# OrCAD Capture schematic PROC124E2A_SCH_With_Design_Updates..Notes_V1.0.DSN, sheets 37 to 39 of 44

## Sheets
37 36. OLDI DISPLAY INTERFACE: size C; title: OLDI DISPLAY INTERFACE
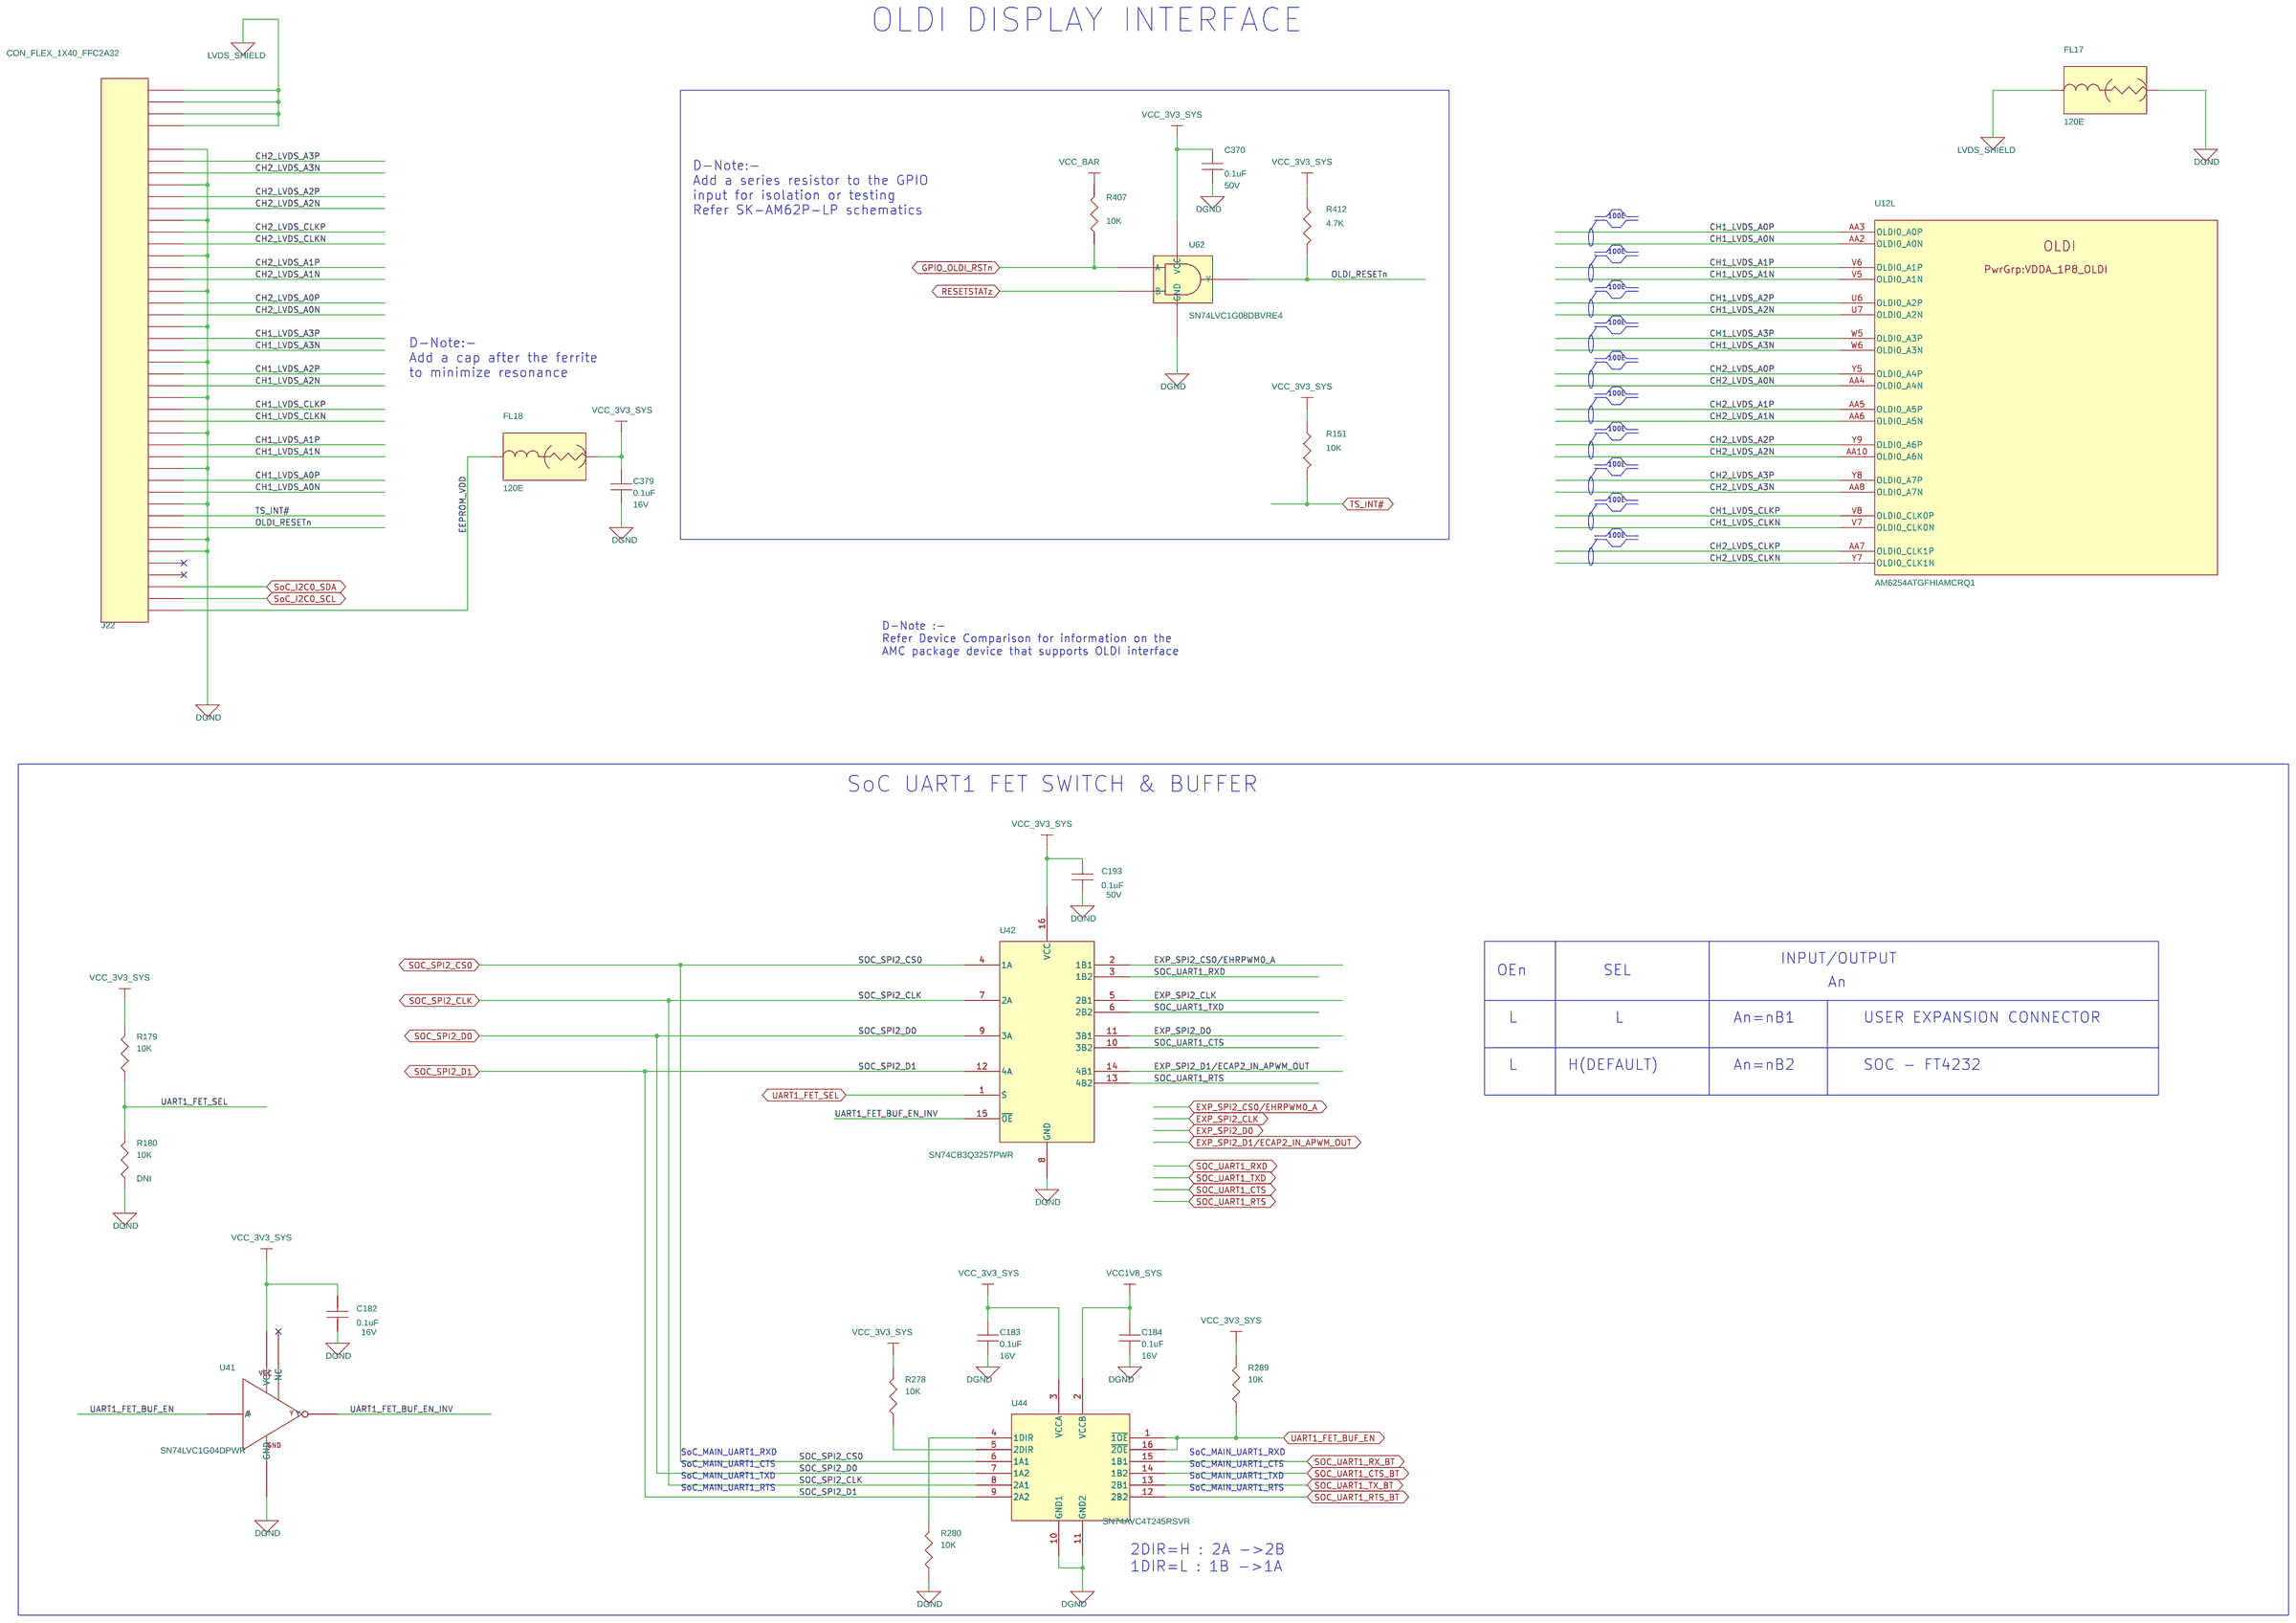
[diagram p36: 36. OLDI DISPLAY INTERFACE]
38 37. CSI INTERFACE & TEST LEDS: size C; title: CSI INTERFACE & USER TEST LEDS
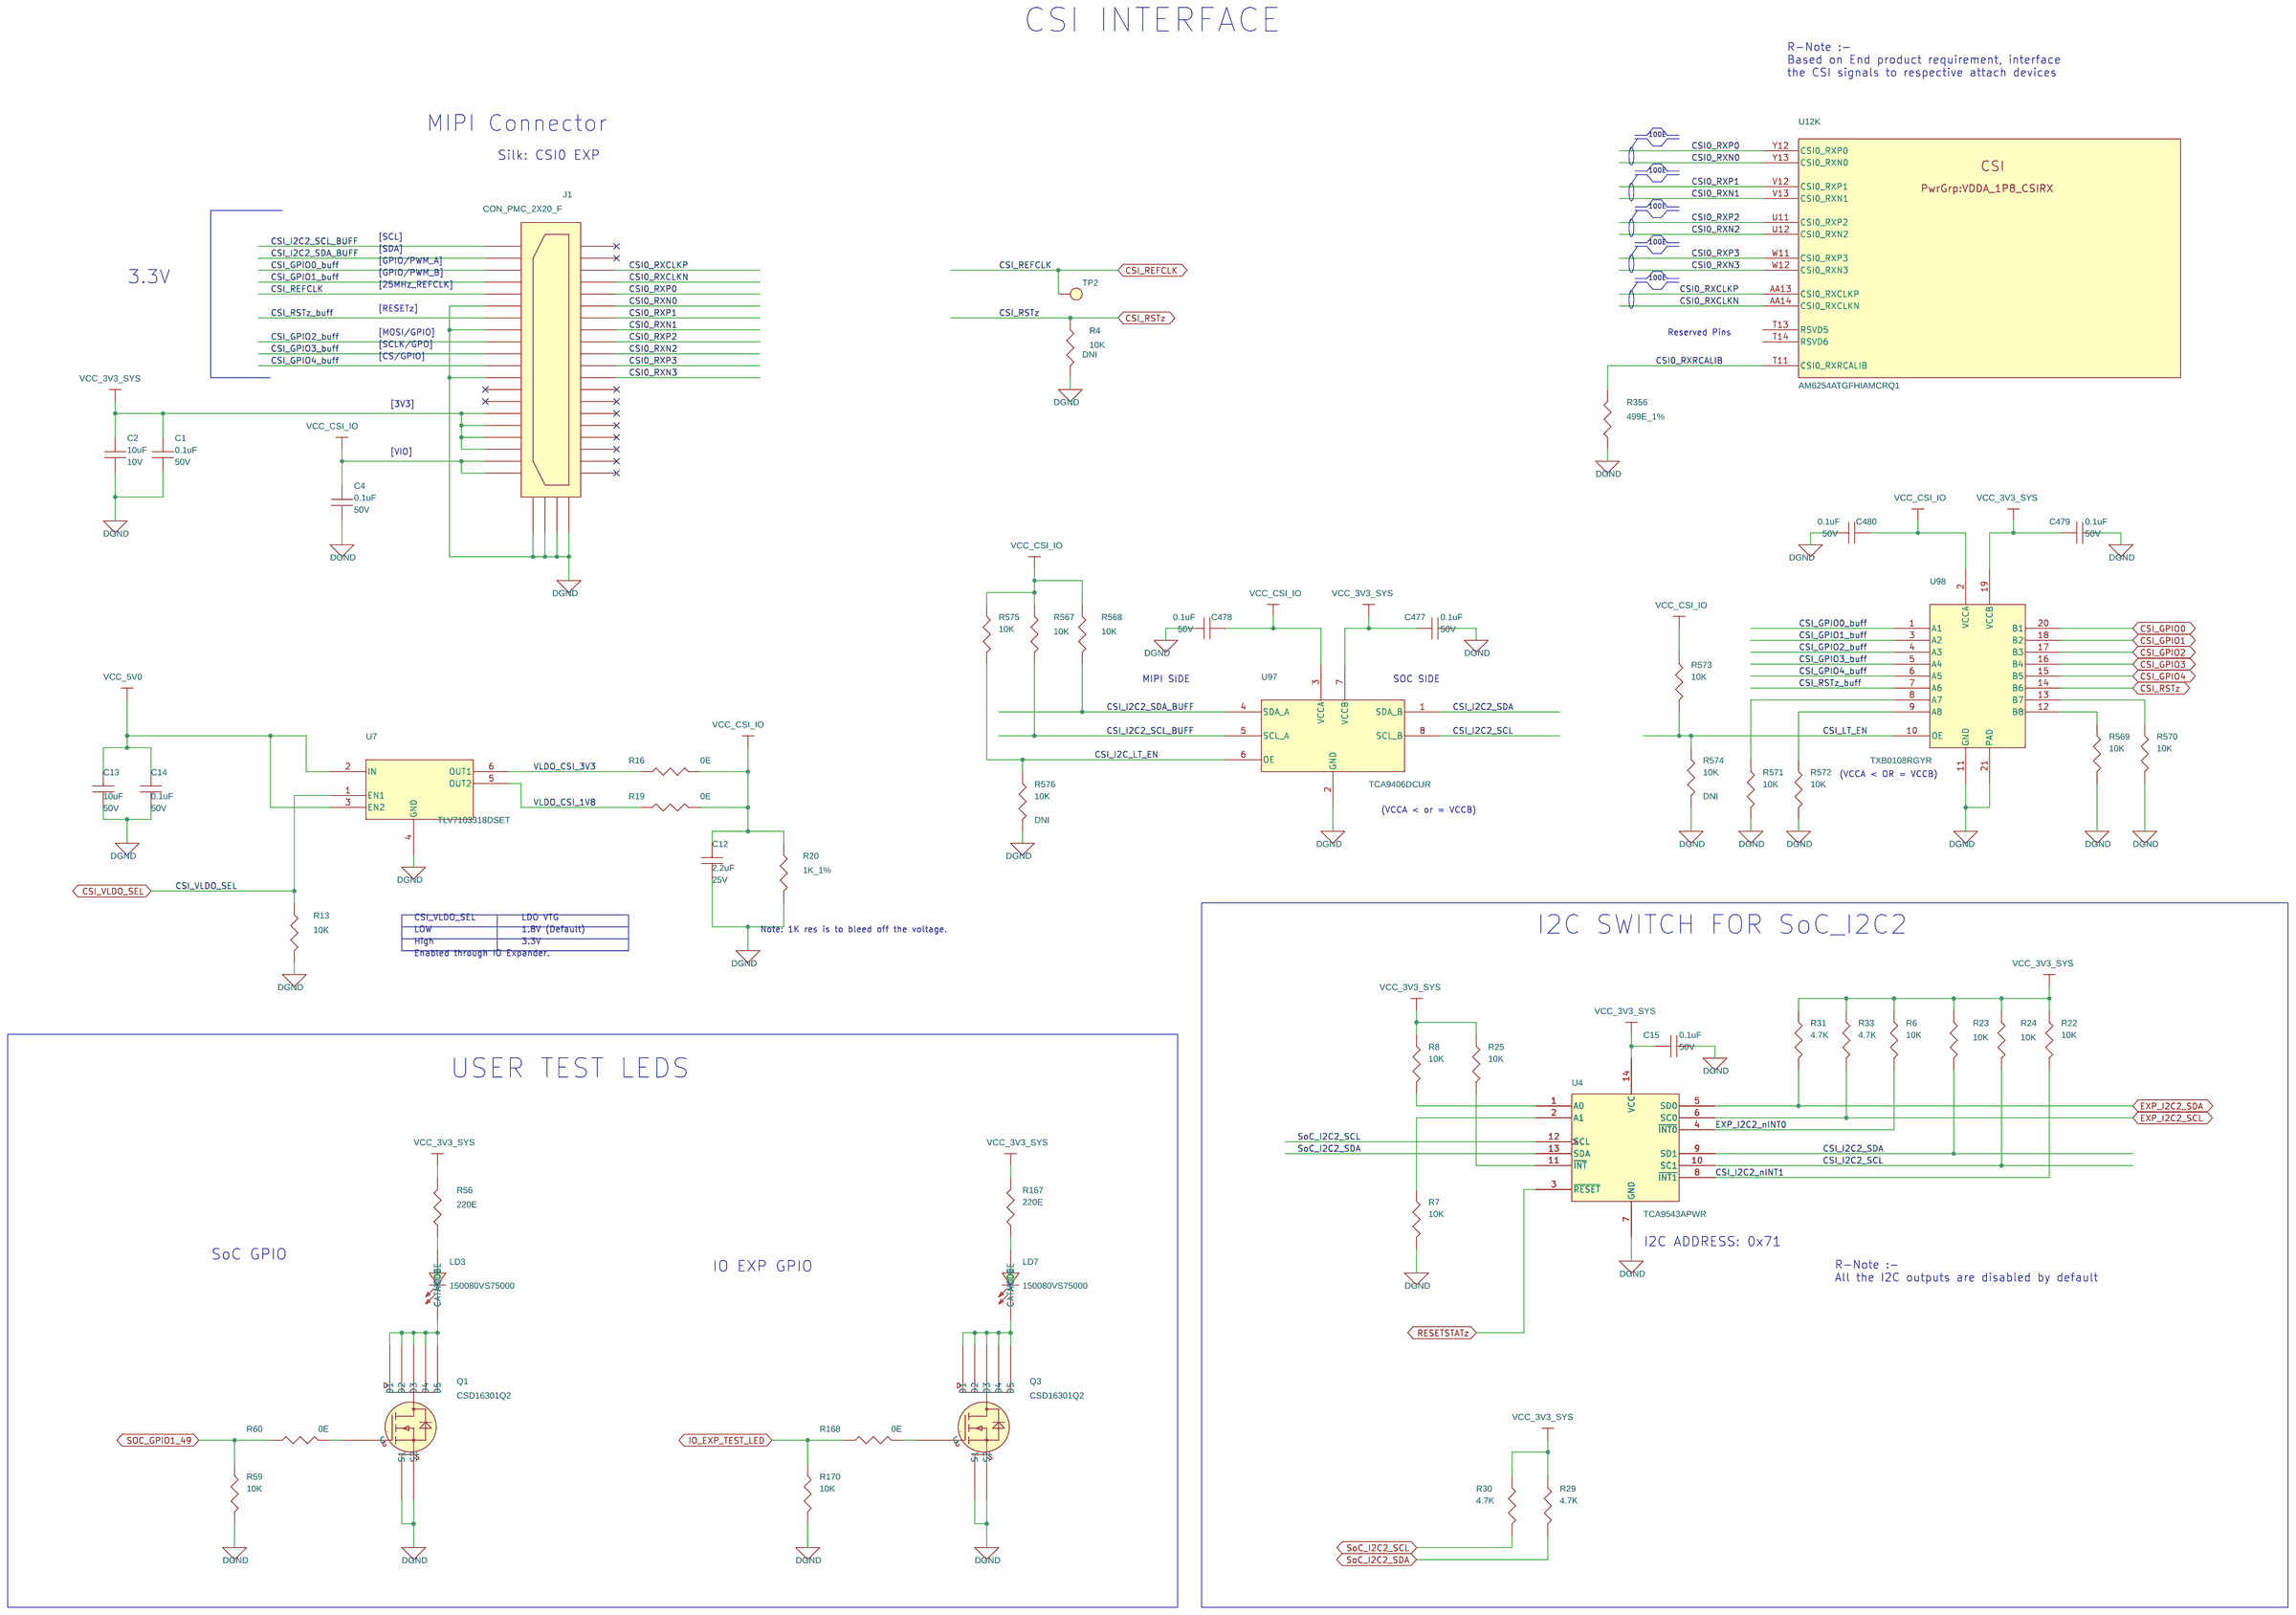
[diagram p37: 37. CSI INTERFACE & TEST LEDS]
39 39. IO EXPANDER: size C; title: IO EXPANDER
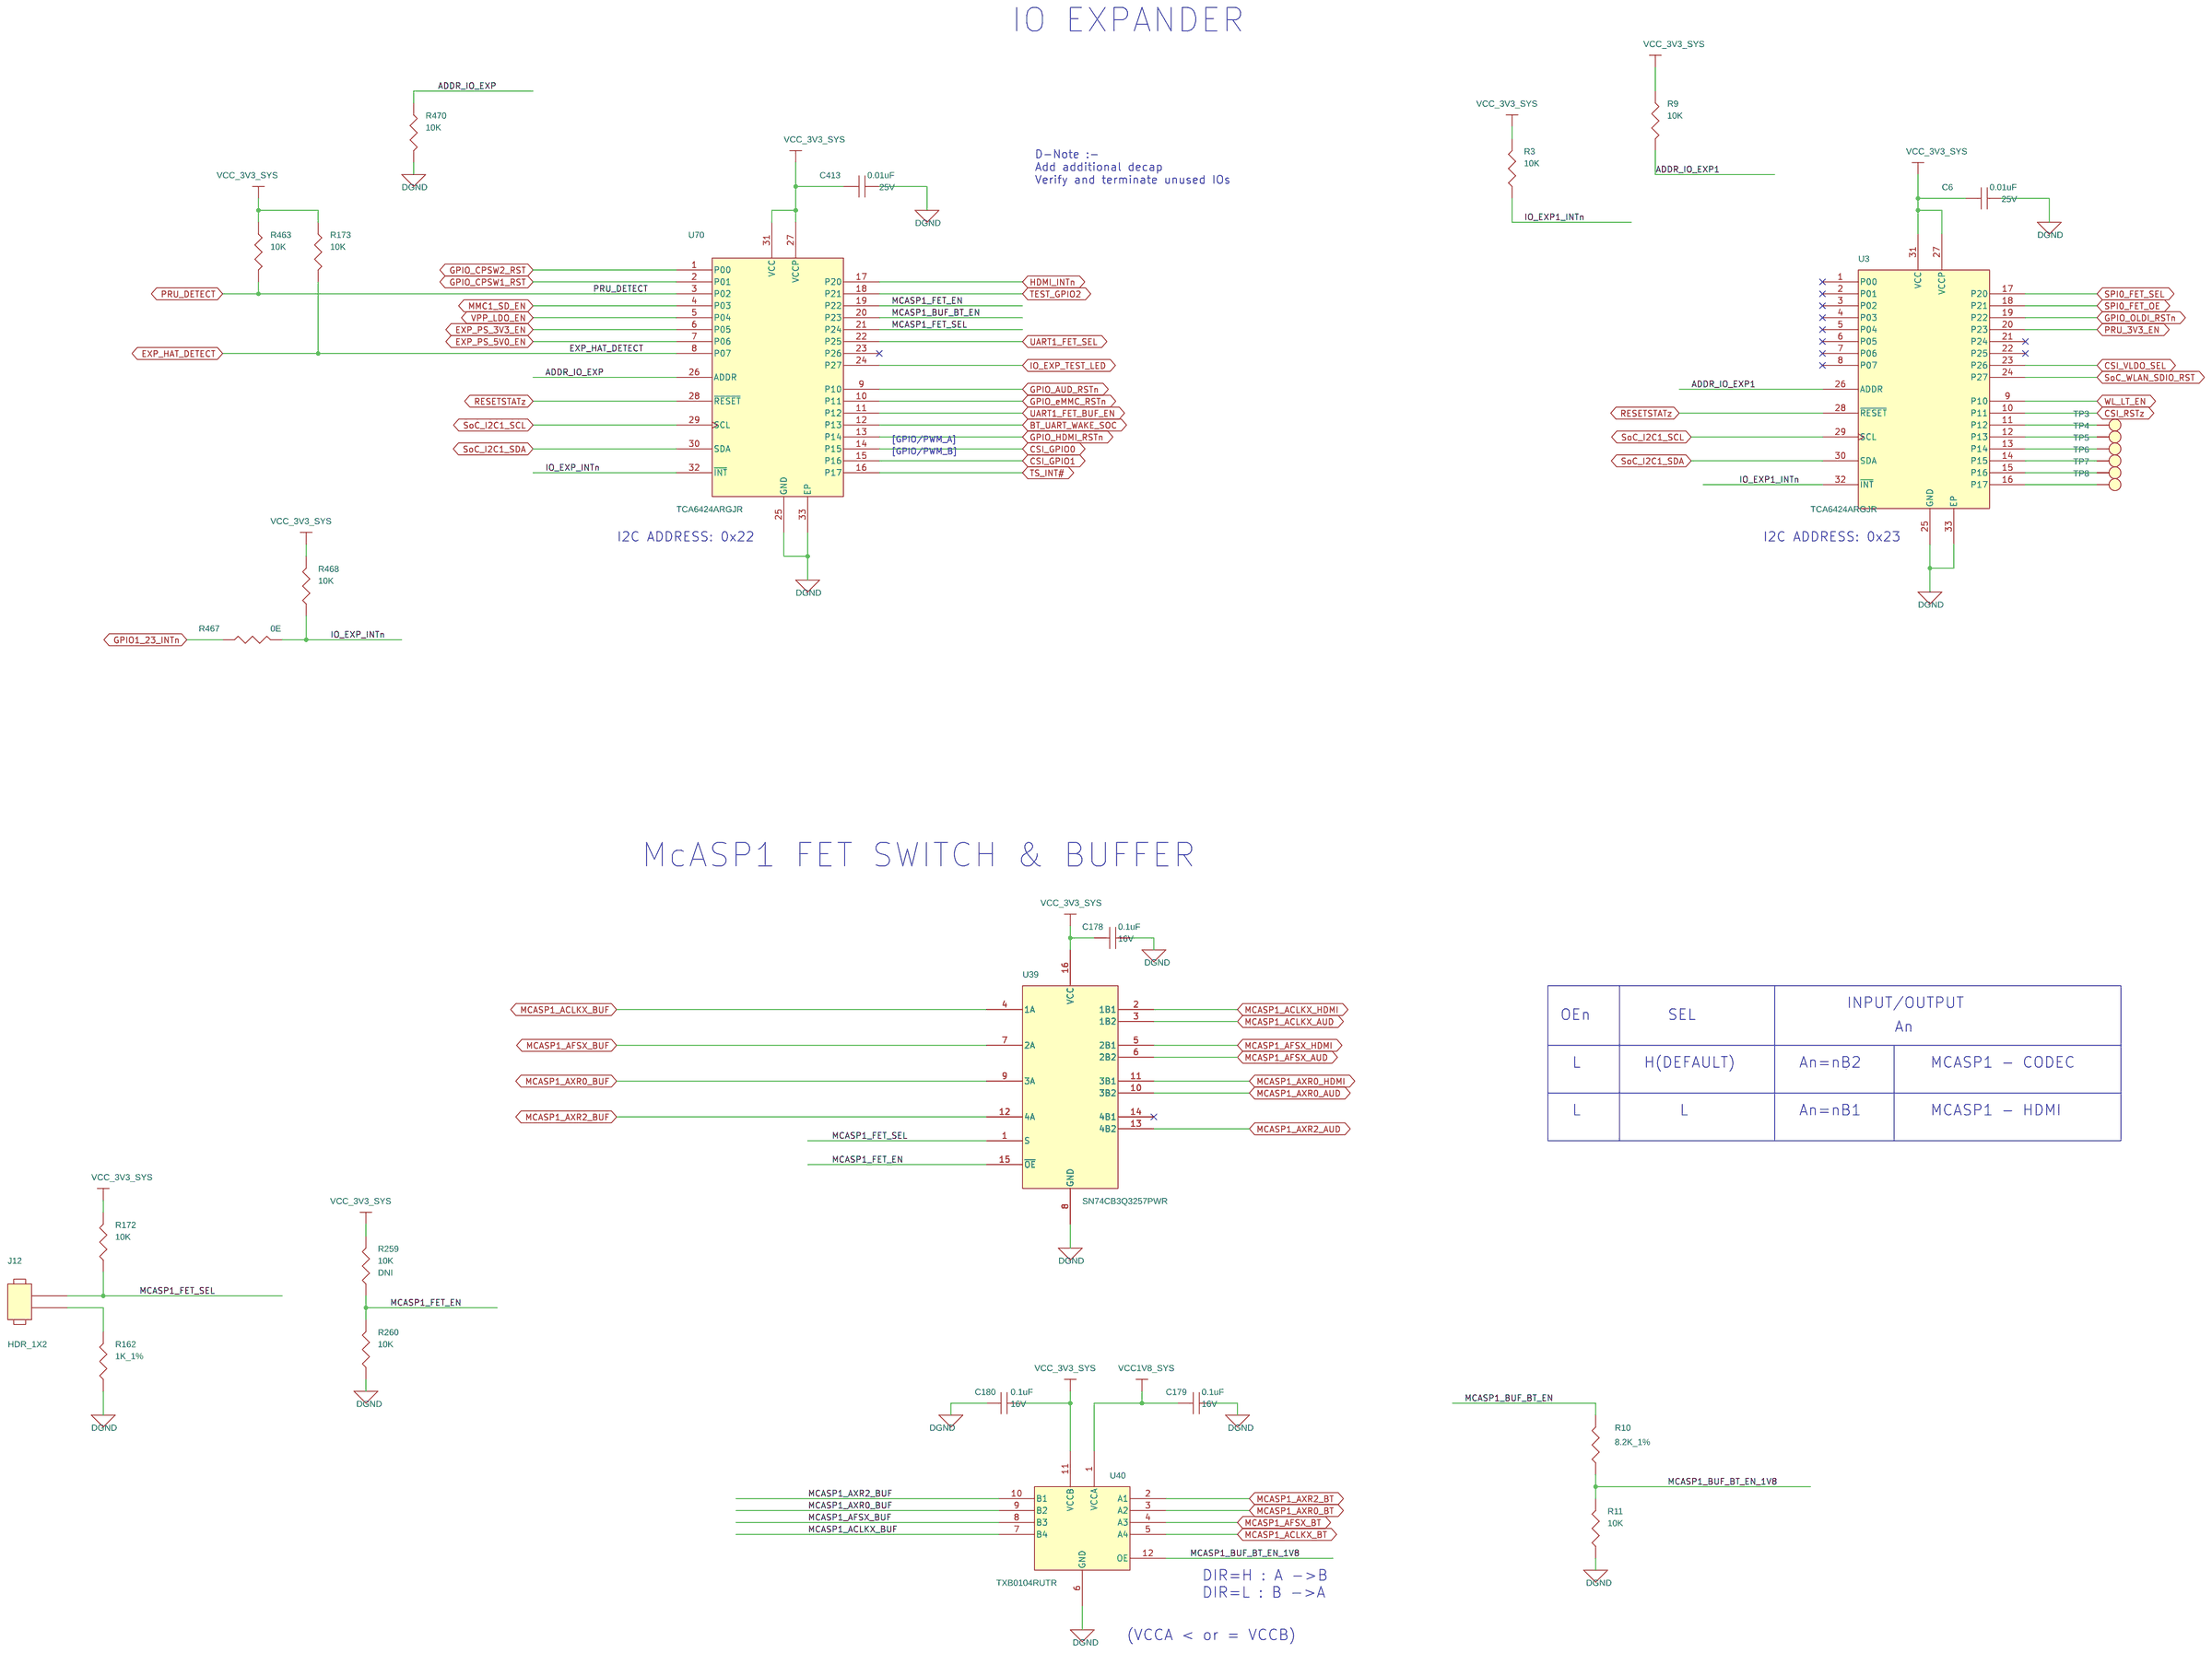
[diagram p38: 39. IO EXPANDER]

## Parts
sheet 15. SOC POWER CAPS
U12  AM6254ATGFHIAMCRQ1  [FCBGA441_31-49_680X680_2-6]  (sections A,B,C,D,E,F,G,H,I,J,K,L,M,N,O,P,Q,R)
sheet 36. OLDI DISPLAY INTERFACE
C182  0.1uF  [CAP0201_0-5]
C183  0.1uF  [CAP0201_0-5]
C184  0.1uF  [CAP0201_0-5]
C193  0.1uF  [CAP0402_0-75]
C370  0.1uF  [CAP0402_0-75]
C379  0.1uF  [CAP0201_0-5]
FL17  120E  [EMIFIL_BLM15A_0402_0-6]
FL18  120E  [EMIFIL_BLM15A_0402_0-6]
J22  CON_FLEX_1X40_FFC2A32  [CON_FLEX1X40_FFC2A32-40-T_S_S_S_4-3]
R151  10K  [RES0201_0-5]
R179  10K  [RES0201_0-5]
R180  10K  [RES0201_0-5]
R278  10K  [RES0201_0-5]
R280  10K  [RES0201_0-5]
R289  10K  [RES0201_0-5]
R407  10K  [RES0201_0-5]
R412  4.7K  [RES0201_0-5]
U41  SN74LVC1G04DPWR  [X2SON5_TLV7021_30X30_0-4]
U42  SN74CB3Q3257PWR  [TSSOP16_25-59_205X180]
U44  SN74AVC4T245RSVR  [UQFN16_TMUX1574_70X100_0-6]
U62  SN74LVC1G08DBVRE4  [SOT23-5]
sheet 37. CSI INTERFACE & TEST LEDS
C1  0.1uF  [CAP0402_0-75]
C2  10uF  [CAP0402_0-75]
C4  0.1uF  [CAP0402_0-75]
C12  2.2uF  [CAP0402_0-75]
C13  10uF  [CAP0805_1-5]
C14  0.1uF  [CAP0402_0-75]
C15  0.1uF  [CAP0402_0-75]
C477  0.1uF  [CAP0402_0-75]
C478  0.1uF  [CAP0402_0-75]
C479  0.1uF  [CAP0402_0-75]
C480  0.1uF  [CAP0402_0-75]
J1  CON_PMC_2X20_F  [CON_PMC2X20_QSH-020-01-D-DP-A_S_S_S_3-4]
LD3  150080VS75000  [LED_150080VS75000_80X50_SMD_0-8]
LD7  150080VS75000  [LED_150080VS75000_80X50_SMD_0-8]
Q1  CSD16301Q2  [WSON6_CSD13202Q2_80X80_0-8]
Q3  CSD16301Q2  [WSON6_CSD13202Q2_80X80_0-8]
R4  10K  [RES0201_0-5]
R6  10K  [RES0201_0-5]
R7  10K  [RES0201_0-5]
R8  10K  [RES0201_0-5]
R13  10K  [RES0201_0-5]
R16  0E  [RES0402_0-5]
R19  0E  [RES0402_0-5]
R20  1K_1%  [RES0402_0-5]
R22  10K  [RES0201_0-5]
R23  10K  [RES0201_0-5]
R24  10K  [RES0201_0-5]
R25  10K  [RES0201_0-5]
R29  4.7K  [RES0201_0-5]
R30  4.7K  [RES0201_0-5]
R31  4.7K  [RES0201_0-5]
R33  4.7K  [RES0201_0-5]
R56  220E  [RES0402_0-5]
R59  10K  [RES0201_0-5]
R60  0E  [RES0402_0-5]
R167  220E  [RES0402_0-5]
R168  0E  [RES0402_0-5]
R170  10K  [RES0201_0-5]
R356  499E_1%  [RES0402_0-5]
R567  10K  [RES0201_0-5]
R568  10K  [RES0201_0-5]
R569  10K  [RES0201_0-5]
R570  10K  [RES0201_0-5]
R571  10K  [RES0201_0-5]
R572  10K  [RES0201_0-5]
R573  10K  [RES0201_0-5]
R574  10K  [RES0201_0-5]
R575  10K  [RES0201_0-5]
R576  10K  [RES0201_0-5]
TP2  TP20_SMD  [TP20_SMD]
U4  TCA9543APWR  [TSSOP14_25-59_205X180_1-2]
U7  TLV7103318DSET  [WSON6_19-68_60X60]
U97  TCA9406DCUR  [VSSOP8_19-68_85X95]
U98  TXB0108RGYR  [QFN20_19-68_185X145_1]
sheet 39. IO EXPANDER
C6  0.01uF  [CAP0201_0-5]
C178  0.1uF  [CAP0201_0-5]
C179  0.1uF  [CAP0201_0-5]
C180  0.1uF  [CAP0201_0-5]
C413  0.01uF  [CAP0201_0-5]
J12  HDR_1X2  [HDR_1X2_90120-0122_S_T_5-6]
R3  10K  [RES0201_0-5]
R9  10K  [RES0201_0-5]
R10  8.2K_1%  [RES0201_0-5]
R11  10K  [RES0201_0-5]
R162  1K_1%  [RES0402_0-5]
R172  10K  [RES0201_0-5]
R173  10K  [RES0201_0-5]
R259  10K  [RES0201_0-5]
R260  10K  [RES0201_0-5]
R463  10K  [RES0201_0-5]
R467  0E  [RES0201_0-5]
R468  10K  [RES0201_0-5]
R470  10K  [RES0201_0-5]
TP3  TP20_SMD  [TP20_SMD]
TP4  TP20_SMD  [TP20_SMD]
TP5  TP20_SMD  [TP20_SMD]
TP6  TP20_SMD  [TP20_SMD]
TP7  TP20_SMD  [TP20_SMD]
TP8  TP20_SMD  [TP20_SMD]
U3  TCA6424ARGJR  [QFN32_19-68_200X200]
U39  SN74CB3Q3257PWR  [TSSOP16_25-59_205X180]
U40  TXB0104RUTR  [UQFN12_TXB0104RUT_70X80_0-6]
U70  TCA6424ARGJR  [QFN32_19-68_200X200]

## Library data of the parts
U12 = AM6254ATGFHIAMCRQ1_FCBGA441: IC AM62Q SoC MICROPROCESSOR FCBGA441; Chkd/date: PRADEEP/180324; Crtd /date: TAMILARASU/180324; Custom_Duty: 15%; Customs_HS_Code: 85423100; Distributor_name: NA; Distributor_part_number: NA; Footprint Path: Y:\MIS_DATABASE\Library\ALTIUM_TOOL\PCB_FOOTPRINTS\Altium_Footprint_Lib.PcbLib; Height: 2.57MM; Library Path: Y:\MIS_DATABASE\Library\ALTIUM_TOOL\SCHEMATICS_PARTS\MS_MICROPROCESSOR_Library.schlib; Mfr_name: TEXAS INSTRUMENTS; Mistral Part No: 141224030001-R; Package: FCBGA441; Part_type: ICS\DIGITAL\MICROPROCESSOR; Project: TI_AM62Q_BRD; RoHS: NA; Temperature: NA; Tolerance: NA; Voltage: NA; Wattage: NA; Weight: NA; Datasheet: Y:\MIS_DATABASE\DATASHEETS\ICS\DIGITAL\MICROCONTROLLER\AM62Q-SoC.PDF
C178-C180 C182-C184 C379 = CAP: CAP CERAMIC 0.1uF 16V 10% X5R 0201; Alt_Mfr_name: YAGEO AMERICA; Alt_Mfr_part_number: CC0402KRX5R8BB104; Chkd/date: MANIRAJA/230118; Crtd /date: MANIRAJA/230118; Custom_Duty: 15%; Customs_HS_Code: 85322990; Distributor_name: DIGIKEY; Distributor_part_number: 490-14305-1-ND; Footprint Path: Y:\MIS_DATABASE\Library\ALTIUM_TOOL\PCB_FOOTPRINTS\Altium_Footprint_Lib.PcbLib; Height: 0.33MM; Library Path: Y:\MIS_DATABASE\Library\ALTIUM_TOOL\SCHEMATICS_PARTS\MS_DISCRETE_Library.schlib; Mfr_name: MURATA; Mfr_part_number: GRM033R61C104KE14D; Mistral Part No: 120009030072-R; Package: 0201; Part_type: CAPACITORS\CERAMIC; Project: TI_MAXIE_CPB; RoHS: RoHS; Temperature: -55°C+85°C; Tolerance: 10%; Voltage: 16V; Wattage: NA; Weight: 0.33mg; Datasheet: Y:\MIS_DATABASE\DATASHEETS\CAPACITORS\GRM033R61C104KE14.PDF
C1 C4 C14 C15 C193 C370 C477-C480 = CAP: CAP CERAMIC 0.1uF 50V 10% X7R 0402; Alt_Mfr_name: YAGEO AMERICA; Alt_Mfr_part_number: CC0402KRX5R8BB104; Chkd/date: MANIRAJA/261020; Crtd /date: ALVY/211020; Custom_Duty: 15%; Customs_HS_Code: 85322990; Distributor_name: DIGIKEY; Distributor_part_number: 490-10700-1-ND; Footprint Path: Y:\MIS_DATABASE\Library\ALTIUM_TOOL\PCB_FOOTPRINTS\Altium_Footprint_Lib.PcbLib; Height: 0.55MM; Library Path: Y:\MIS_DATABASE\Library\ALTIUM_TOOL\SCHEMATICS_PARTS\MS_DISCRETE_Library.schlib; Mfr_name: MURATA; Mfr_part_number: GRM155R71H104KE14D; Mistral Part No: 120011100014-R; Package: 0402; Part_type: CAPACITORS\CERAMIC; Project: J7_CP; RoHS: RoHS; Temperature: -55°C+125°C; Tolerance: 10%; Voltage: 50V; Wattage: NA; Weight: 3.1mg; Datasheet: Y:\MIS_DATABASE\DATASHEETS\CAPACITORS\GRM155R71H104KE14.PDF
FL17 FL18 = EMIFILTER_IND: IND FERRITE BEAD CHIP 120E 2A 0402; Chkd/date: NAVEED/241114; Crtd /date: USMAN/170613; Custom_Duty: 24%; Customs_HS_Code: 85369090; Distributor_name: DIGIKEY; Distributor_part_number: 490-9656-1-ND; Footprint Path: Y:\MIS_DATABASE\Library\ALTIUM_TOOL\PCB_FOOTPRINTS\Altium_Footprint_Lib.PcbLib; Height: 0.55MM; Library Path: Y:\MIS_DATABASE\Library\ALTIUM_TOOL\SCHEMATICS_PARTS\MS_FILTER_Library.schlib; Mfr_name: MURATA; Mfr_part_number: BLM15PX121SN1D; Mistral Part No: 130013060022-R; Package: 0402; Part_type: INDUCTOR; Project: GEN_3-8; RoHS: RoHS; Temperature: -55°C+125°C; Tolerance: 25%; Voltage: NA; Wattage: NA; Weight: 1mg; Datasheet: Y:\MIS_DATABASE\DATASHEETS\DISCRETES\INDUCTORS\BLM15-SN1-SER.PDF
J22 = CON_FLEX_40X1_SH4: CON FPC 1X40 0.50MM PITCH FEMALE ST SMD; Chkd/date: MANIRAJA/061021; Crtd /date: ALVY/041021; Custom_Duty: 24%; Customs_HS_Code: 85369090; Distributor_name: DIGIKEY; Distributor_part_number: 2073-FFC2A32-40-TCT-ND; Footprint Path: Y:\MIS_DATABASE\Library\ALTIUM_TOOL\PCB_FOOTPRINTS\Altium_Footprint_Lib.PcbLib; Height: 4.25MM; Library Path: Y:\MIS_DATABASE\Library\ALTIUM_TOOL\SCHEMATICS_PARTS\MS_CONNECTOR_Library.schlib; Mfr_name: GCT; Mfr_part_number: FFC2A32-40-T; Mistral Part No: 150021100004-R; Package: SMD; Part_type: CONNECTOR\FPC; Project: TI_AM62x SKEVM_BRD; RoHS: RoHS; Temperature: -25°C+85°C; Tolerance: NA; Voltage: NA; Wattage: NA; Weight: 710mg; Datasheet: Y:\MIS_DATABASE\DATASHEETS\CONNECTORS\FFC2A32.PDF
R3 R6-R9 R11 R13 R22-R25 R59 R151 R170 R172 R173 R179 R260 R278 R280 R289 R407 R463 R468 R470 R567-R573 R575 = RESISTOR: RES 10K 1/20W 5% 0201; Chkd/date: MANIRAJA/050517; Crtd /date: MANIRAJA/050517; Custom_Duty: 15%; Customs_HS_Code: 85332119; Distributor_name: DIGIKEY; Distributor_part_number: 311-10KNCT-ND; Footprint Path: Y:\MIS_DATABASE\Library\ALTIUM_TOOL\PCB_FOOTPRINTS\Altium_Footprint_Lib.PcbLib; Height: 0.26MM; Library Path: Y:\MIS_DATABASE\Library\ALTIUM_TOOL\SCHEMATICS_PARTS\MS_DISCRETE_Library.schlib; Mfr_name: YAGEO AMERICA; Mfr_part_number: RC0201JR-0710KL; Mistral Part No: 110010070051-R; Package: 0201; Part_type: RESISTORS\FIXED; Project: GOLDEN-I LITE; RoHS: RoHS; Temperature: -55°C+125°C; Tolerance: 5%; Voltage: NA; Wattage: 1/20W; Weight: 0.17mg; Datasheet: Y:\MIS_DATABASE\DATASHEETS\RESISTORS\RCXXXXL-SER_MAR18.PDF
R4 R180 R259 R574 R576 = RESISTOR: RES 10K 1/20W 5% 0201; Assembly_Instruction: DNI; Chkd/date: MANIRAJA/050517; Crtd /date: MANIRAJA/050517; Custom_Duty: 15%; Customs_HS_Code: 85332119; Distributor_name: DIGIKEY; Distributor_part_number: 311-10KNCT-ND; Footprint Path: Y:\MIS_DATABASE\Library\ALTIUM_TOOL\PCB_FOOTPRINTS\Altium_Footprint_Lib.PcbLib; Height: 0.26MM; Library Path: Y:\MIS_DATABASE\Library\ALTIUM_TOOL\SCHEMATICS_PARTS\MS_DISCRETE_Library.schlib; Mfr_name: YAGEO AMERICA; Mfr_part_number: RC0201JR-0710KL; Mistral Part No: 110010070051-R; Package: 0201; Part_type: RESISTORS\FIXED; Project: GOLDEN-I LITE; RoHS: RoHS; Temperature: -55°C+125°C; Tolerance: 5%; Voltage: NA; Wattage: 1/20W; Weight: 0.17mg; Datasheet: Y:\MIS_DATABASE\DATASHEETS\RESISTORS\RCXXXXL-SER_MAR18.PDF
R29-R31 R33 R412 = RESISTOR: RES 4.7K 1/20W 5% 0201; Chkd/date: MANIRAJA/200921; Crtd /date: ALVY/200921; Custom_Duty: 15%; Customs_HS_Code: 85332119; Distributor_name: DIGIKEY; Distributor_part_number: 311-4.7KNCT-ND; Footprint Path: Y:\MIS_DATABASE\Library\ALTIUM_TOOL\PCB_FOOTPRINTS\Altium_Footprint_Lib.PcbLib; Height: 0.26MM; Library Path: Y:\MIS_DATABASE\Library\ALTIUM_TOOL\SCHEMATICS_PARTS\MS_DISCRETE_Library.schlib; Mfr_name: YAGEO AMERICA; Mfr_part_number: RC0201JR-074K7L; Mistral Part No: 110021090007-R; Package: 0201; Part_type: RESISTORS\FIXED; Project: TI_AM62x SKEVM_BRD; RoHS: RoHS; Temperature: -55°C+125°C; Tolerance: 5%; Voltage: NA; Wattage: 1/20W; Weight: 0.17mg; Datasheet: Y:\MIS_DATABASE\DATASHEETS\RESISTORS\RCXXXXL-SER_MAR18.PDF
U41 = SN74LVC1G04DCKR_SC70-5: IC SINGLE INVERTER GATE X2SON5; Chkd/date: MANIRAJA/141020; Crtd /date: ALVY/131020; Custom_Duty: 15%; Customs_HS_Code: 85423100; Distributor_name: DIGIKEY; Distributor_part_number: 296-37758-1-ND; Footprint Path: Y:\MIS_DATABASE\Library\ALTIUM_TOOL\PCB_FOOTPRINTS\Altium_Footprint_Lib.PcbLib; Height: 0.40MM; Library Path: Y:\MIS_DATABASE\Library\ALTIUM_TOOL\SCHEMATICS_PARTS\MS_GATE_Library.schlib; Mfr_name: TEXAS INSTRUMENTS; Mistral Part No: 141020100010-R; Package: X2SON5; Part_type: ICS\DIGITAL\GATES; Project: AM64X_SKEVM; RoHS: RoHS; Temperature: -40°C+125°C; Tolerance: NA; Voltage: NA; Wattage: NA; Weight: 0.6mg; Datasheet: Y:\MIS_DATABASE\DATASHEETS\ICS\DIGITAL\GATES\SN74LVC1G04XX.PDF
U42 = SN74CB3Q3257PWR_TSSOP16: IC 4BIT 1-OF-2 FET MULTIPLEXER/DEMULTIPLEXER TSSOP16; Chkd/date: SUHAS/251010; Crtd /date: USMAN/060109; Custom_Duty: 15%; Customs_HS_Code: 85423100; Distributor_name: DIGIKEY; Distributor_part_number: 296-19138-1-ND; Footprint Path: Y:\MIS_DATABASE\Library\ALTIUM_TOOL\PCB_FOOTPRINTS\Altium_Footprint_Lib.PcbLib; Footprint Ref: TSSOP16_25-59_205X180_1-2; Height: 1.20MM; Library Path: Y:\MIS_DATABASE\Library\ALTIUM_TOOL\SCHEMATICS_PARTS\MS_COMBINATIONAL_Library.schlib; MECHANICAL 3D STEP FILE: TSSOP16_25-59_205X180_1-2; Mfr_name: TEXAS INSTRUMENTS; Mistral Part No: 141009030117-R; Package: TSSOP16; Part_type: ICS\DIGITAL\COMBINATIONAL; Project: OMAP_EVM; RoHS: Sb/ Br FREE; Temperature: -40°C+85°C; Datasheet: Y:\MIS_DATABASE\DATASHEETS\ICS\DIGITAL\COMBINATIONAL\SN74CB3Q3257.PDF
U44 = SN74AVC4T245RSV_UQFN16: IC 2-BIT BUS TRANSCEIVER WITH CONFIGURABLE VOLTAGE TRANSLATION AND 3 STATE O/P UQFN16; Chkd/date: MANIRAJA/040520; Crtd /date: BAVISH/190411; Custom_Duty: 15%; Customs_HS_Code: 85423100; Distributor_name: DIGIKEY; Distributor_part_number: 296-24366-1-ND; Footprint Path: Y:\MIS_DATABASE\Library\ALTIUM_TOOL\PCB_FOOTPRINTS\Altium_Footprint_Lib.PcbLib; Height: 0.55MM; Library Path: Y:\MIS_DATABASE\Library\ALTIUM_TOOL\SCHEMATICS_PARTS\MS_BUSDRIVERTRANSCEIVER_Library.schlib; Mfr_name: TEXAS INSTRUMENTS; Mistral Part No: 141011040011-R; Package: UQFN16; Part_type: ICS\DIGITAL\BUSTRANSCEIVER; Project: HMC; RoHS: RoHS; Temperature: -40°C+85°C; Tolerance: NA; Voltage: NA; Wattage: NA; Weight: 41mg; Datasheet: Y:\MIS_DATABASE\DATASHEETS\ICS\DIGITAL\BUSTRANSCEIVER\SN74AVC4T245-SER.PDF
U62 = SN74LVC1G08DBVRE4_SOT23-5: IC SINGLE 2-INPUT POSITIVE AND GATE SOT23-5; Chkd/date: SUHAS/221010; Crtd /date: USMAN/151008; Custom_Duty: 15%; Customs_HS_Code: 85423100; Distributor_name: DIGIKEY; Distributor_part_number: SN74LVC1G08DBVRE4-ND; Height: 1.45MM; Mfr_name: TEXAS INSTRUMENTS; Mistral Part No: 141009060026-R; Part_type: ICS\DIGITAL\GATES; Project: KHAN_MAIN; RoHS: Sb/ Br FREE; Temperature: -40°C+85°C; Datasheet: Y:\MIS_DATABASE\DATASHEETS\ICS\DIGITAL\GATES\SN74LVC1G08.PDF
C2 = CAP: CAP CERAMIC 10uF 10V 20% X5R 0402; Chkd/date: MANIRAJA/300520; Crtd /date: ALVY/260520; Custom_Duty: 15%; Customs_HS_Code: 85322990; Distributor_name: DIGIKEY; Distributor_part_number: 490-GRM155R61A106ME11DTR-ND; Footprint Path: Y:\MIS_DATABASE\Library\ALTIUM_TOOL\PCB_FOOTPRINTS\Altium_Footprint_Lib.PcbLib; Height: 0.55MM; Library Path: Y:\MIS_DATABASE\Library\ALTIUM_TOOL\SCHEMATICS_PARTS\MS_DISCRETE_Library.schlib; Mfr_name: MURATA; Mfr_part_number: GRM155R61A106ME11D; Mistral Part No: 120013110019-R; Package: 0402; Part_type: CAPACITORS\CERAMIC; Project: QCS610_NANOSOM; RoHS: RoHS; Temperature: -55°C+85°C; Tolerance: 20%; Voltage: 10V; Wattage: NA; Weight: 3.1mg; Datasheet: Y:\MIS_DATABASE\DATASHEETS\CAPACITORS\MURATA-GXX-SER_NOV17.PDF
C12 = CAP: CAP CERAMIC 2.2uF 25V 10% X5R 0402; Chkd/date: ALVY/010721; Crtd /date: MANIRAJA/010721; Custom_Duty: 15%; Customs_HS_Code: 85322990; Distributor_name: DIGIKEY; Distributor_part_number: 490-12703-1-ND; Footprint Path: Y:\MIS_DATABASE\Library\ALTIUM_TOOL\PCB_FOOTPRINTS\Altium_Footprint_Lib.PcbLib; Height: 0.70MM; Library Path: Y:\MIS_DATABASE\Library\ALTIUM_TOOL\SCHEMATICS_PARTS\MS_DISCRETE_Library.schlib; Manufacturer: MURATA; Mfr_name: MURATA; Mfr_part_number: GRM155R61E225KE11D; Mistral Part No: 120015120001-R; Package: 0402; Part_type: CAPACITORS\CERAMIC; Project: TI_AM263X_CC; RoHS: RoHS; Temperature: -55°C+85°C; Tolerance: 10%; Voltage: 25V; Wattage: NA; Weight: 1.5mg; Datasheet: Y:\MIS_DATABASE\DATASHEETS\CAPACITORS\GRM155R61E225KE11.PDF
C13 = CAP: CAP CERAMIC 10uF 50V 10% X5R 0805; Chkd/date: MANIRAJA/010321; Crtd /date: ALVY/010321; Custom_Duty: 15%; Customs_HS_Code: 85322990; Distributor_name: DIGIKEY; Distributor_part_number: 490-18663-1-ND; Footprint Path: Y:\MIS_DATABASE\Library\ALTIUM_TOOL\PCB_FOOTPRINTS\Altium_Footprint_Lib.PcbLib; Height: 1.45MM; Library Path: Y:\MIS_DATABASE\Library\ALTIUM_TOOL\SCHEMATICS_PARTS\MS_DISCRETE_Library.schlib; Manufacturer: MURATA; Mfr_name: MURATA; Mfr_part_number: GRM21BR61H106KE43L; Mistral Part No: 120021030002-R; Package: 0805; Part_type: CAPACITORS\CERAMIC; Project: J7ES_SK_BRD; RoHS: RoHS; Temperature: -55°C+85°C; Tolerance: 10%; Voltage: 50V; Wattage: NA; Weight: 6.4mg; Datasheet: Y:\MIS_DATABASE\DATASHEETS\CAPACITORS\GRM21BR61H106KE43.PDF
J1 = CON_PMC_20X2_F_DP_TI: CON PMC 2X20 0.50MM PITCH FEMALE ST SMD; Chkd/date: MANIRAJA/251018; Crtd /date: ALVY/251018; Custom_Duty: 24%; Customs_HS_Code: 85369090; Distributor_name: DIGIKEY; Distributor_part_number: SAM10648-ND; Footprint Path: Y:\MIS_DATABASE\Library\ALTIUM_TOOL\PCB_FOOTPRINTS\Altium_Footprint_Lib.PcbLib; Height: 3.33MM; Library Path: Y:\MIS_DATABASE\Library\ALTIUM_TOOL\SCHEMATICS_PARTS\MS_CONNECTOR_Library.schlib; Library Ref: CON_PMC_20X2_F_DP; Mfr_name: SAMTEC; Mfr_part_number: QSH-020-01-L-D-DP-A-K; Mistral Part No: 150018100049-R; Package: SMD; Part_type: CONNECTOR\PMC; Project: TI_J7ES_EVM_CP; RoHS: RoHS; Temperature: -55°C+125°C; Tolerance: NA; Voltage: NA; Wattage: NA; Weight: NA; Datasheet: Y:\MIS_DATABASE\DATASHEETS\CONNECTORS\QSH-SERIES.PDF
LD3 LD7 = DIODE_LED: DIODE LED BRIGHT GREEN SMD; Chkd/date: MANIRAJA/180820; Crtd /date: ALVY/180820; Custom_Duty: 24%; Customs_HS_Code: 85439000; Distributor_name: DIGIKEY; Distributor_part_number: 732-4986-1-ND; Footprint Path: Y:\MIS_DATABASE\Library\ALTIUM_TOOL\PCB_FOOTPRINTS\Altium_Footprint_Lib.PcbLib; Height: 0.80MM; Library Path: Y:\MIS_DATABASE\Library\ALTIUM_TOOL\SCHEMATICS_PARTS\MS_OPTO_Library.schlib; Mfr_name: WURTH ELECTRONICS; Mistral Part No: 130020080012-R; Package: SMD; Part_type: OPTO\LED; Project: AM64x_EVM_BRD; RoHS: RoHS; Temperature: -40°C+85°C; Tolerance: NA; Voltage: NA; Wattage: NA; Weight: 10mg; Datasheet: Y:\MIS_DATABASE\DATASHEETS\DISCRETES\LEDS\150080VS75000.PDF
Q1 Q3 = MOSFET_CSD17313Q2: IC MOSFET N-CHANNEL NEXFET 25V WSON6; Chkd/date: ALVY/071220; Crtd /date: MANIRAJA/071220; Custom_Duty: 15%; Customs_HS_Code: 85423100; Distributor_name: DIGIKEY; Distributor_part_number: 296-25260-1-ND; Footprint Path: Y:\MIS_DATABASE\Library\ALTIUM_TOOL\PCB_FOOTPRINTS\Altium_Footprint_Lib.PcbLib; Height: 0.80MM; Library Path: Y:\MIS_DATABASE\Library\ALTIUM_TOOL\SCHEMATICS_PARTS\MS_MOSFET_Library.schlib; Manufacturer: TEXAS INSTRUMENTS; Mfr_name: TEXAS INSTRUMENTS; Mistral Part No: 142020120008-R; Package: WSON6; Part_type: ICS\POWER\MOSFET; Project: TI_AM243x LP EVM; RoHS: RoHS; Temperature: -55°C+150°C; Tolerance: NA; Voltage: NA; Wattage: NA; Weight: 8.7mg; Datasheet: Y:\MIS_DATABASE\DATASHEETS\ICS\POWER\CSD16301Q2.PDF
R16 R19 = RESISTOR: RES 0E 1/16W JUMPER 0402; Chkd/date: VASANTHA/201216; Crtd /date: MUDDU/190810; Custom_Duty: 15%; Customs_HS_Code: 85332119; Distributor_name: DIGIKEY; Distributor_part_number: 541-0.0JCT-ND; Footprint Path: Y:\MIS_DATABASE\Library\ALTIUM_TOOL\PCB_FOOTPRINTS\Altium_Footprint_Lib.PcbLib; Height: 0.40MM; Library Path: Y:\MIS_DATABASE\Library\ALTIUM_TOOL\SCHEMATICS_PARTS\MS_DISCRETE_Library.schlib; Manufacturer: VISHAY; Mfr_name: VISHAY; Mfr_part_number: CRCW04020000Z0ED; Mistral Part No: 110010080019-R; Package: 0402; Part_type: RESISTORS\FIXED; Project: PB_BUGBASE; RoHS: RoHS; Temperature: -55°C+155°C; Tolerance: NA; Voltage: NA; Wattage: 1/16W; Weight: 0.65mg; Datasheet: Y:\MIS_DATABASE\DATASHEETS\RESISTORS\CRCW0603.PDF
R20 R162 = RESISTOR: RES 1K 1/10W 1% 0402; Chkd/date: VASANTHA/281216; Crtd /date: MAZHAR/150506; Custom_Duty: 15%; Customs_HS_Code: 85332119; Distributor_name: DIGIKEY; Distributor_part_number: P1.00KLCT-ND; Footprint Path: Y:\MIS_DATABASE\Library\ALTIUM_TOOL\PCB_FOOTPRINTS\Altium_Footprint_Lib.PcbLib; Height: 0.40MM; Library Path: Y:\MIS_DATABASE\Library\ALTIUM_TOOL\SCHEMATICS_PARTS\MS_DISCRETE_Library.schlib; Mfr_name: PANASONIC-ECG; Mfr_part_number: ERJ-2RKF1001X; Mistral Part No: 110009030411-R; Package: 0402; Part_type: RESISTORS\FIXED; Project: VOCERA; RoHS: RoHS; Temperature: -55°C+155°C; Tolerance: 1%; Voltage: NA; Wattage: 1/10W; Weight: 0.8mg; Datasheet: Y:\MIS_DATABASE\DATASHEETS\RESISTORS\PAN-ERJSER_NOV17.PDF
R56 R167 = RESISTOR: RES 220E 1/10W 5% 0402; Chkd/date: VASANTHA/291216; Crtd /date: GEETHA/260406; Custom_Duty: 15%; Customs_HS_Code: 85332119; Distributor_name: DIGIKEY; Distributor_part_number: P220JCT-ND; Footprint Path: Y:\MIS_DATABASE\Library\ALTIUM_TOOL\PCB_FOOTPRINTS\Altium_Footprint_Lib.PcbLib; Height: 0.40MM; Library Path: Y:\MIS_DATABASE\Library\ALTIUM_TOOL\SCHEMATICS_PARTS\MS_DISCRETE_Library.schlib; Mfr_name: PANASONIC-ECG; Mfr_part_number: ERJ-2GEJ221X; Mistral Part No: 110009030506-R; Package: 0402; Part_type: RESISTORS\FIXED; Project: RED EYE; RoHS: RoHS; Temperature: -55°C+155°C; Tolerance: 5%; Voltage: NA; Wattage: 1/10W; Weight: 0.8mg; Datasheet: Y:\MIS_DATABASE\DATASHEETS\RESISTORS\PAN-ERJSER_NOV17.PDF
R60 R168 = RESISTOR: RES 0E 1/16W JUMPER 0402; Chkd/date: VASANTHA/201216; Crtd /date: MUDDU/190810; Custom_Duty: 15%; Customs_HS_Code: 85332119; Distributor_name: DIGIKEY; Distributor_part_number: 541-0.0JCT-ND; Footprint Path: Y:\MIS_DATABASE\Library\ALTIUM_TOOL\PCB_FOOTPRINTS\Altium_Footprint_Lib.PcbLib; Height: 0.40MM; Library Path: Y:\MIS_DATABASE\Library\ALTIUM_TOOL\SCHEMATICS_PARTS\MS_DISCRETE_Library.schlib; Mfr_name: VISHAY; Mfr_part_number: CRCW04020000Z0ED; Mistral Part No: 110010080019-R; Package: 0402; Part_type: RESISTORS\FIXED; Project: PB_BUGBASE; RoHS: RoHS; Temperature: -55°C+155°C; Tolerance: NA; Voltage: NA; Wattage: 1/16W; Weight: 0.65mg; Datasheet: Y:\MIS_DATABASE\DATASHEETS\RESISTORS\CRCW0603.PDF
R356 = RESISTOR: RES 499E 1/16W 1% 0402; Chkd/date: MANIRAJA/051020; Crtd /date: ALVY/051020; Custom_Duty: 15%; Customs_HS_Code: 85332119; Distributor_name: DIGIKEY; Distributor_part_number: 311-499LRCT-ND; Footprint Path: Y:\MIS_DATABASE\Library\ALTIUM_TOOL\PCB_FOOTPRINTS\Altium_Footprint_Lib.PcbLib; Height: 0.40MM; Library Path: Y:\MIS_DATABASE\Library\ALTIUM_TOOL\SCHEMATICS_PARTS\MS_DISCRETE_Library.schlib; Mfr_name: YAGEO AMERICA; Mfr_part_number: RC0402FR-07499RL; Mistral Part No: 110020080006-R; Package: 0402; Part_type: RESISTORS\FIXED; Project: AM64XX_EVM; RoHS: RoHS; Temperature: -55°C+155°C; Tolerance: 1%; Voltage: NA; Wattage: 1/16W; Weight: 0.65mg; Datasheet: Y:\MIS_DATABASE\DATASHEETS\RESISTORS\RCXXXXL-SER_MAR18.PDF
TP2 = TESTPOINT: TESTPOINT CIR 20 SMD; Chkd/date: SHREESHAIL/171006; Crtd /date: MAZHAR/171006; Custom_Duty: NA; Customs_HS_Code: NA; Distributor_name: NA; Distributor_part_number: NA; Footprint Path: Y:\MIS_DATABASE\Library\ALTIUM_TOOL\PCB_FOOTPRINTS\Altium_Footprint_Lib.PcbLib; Height: NA; Library Path: Y:\MIS_DATABASE\Library\ALTIUM_TOOL\SCHEMATICS_PARTS\MS_DISCRETE_Library.schlib; MECHANICAL 3D STEP FILE: NA; Mfr_name: LOCAL; Mistral Part No: NA; Package: SMD; Project: BT MODULE_CSRBC04; RoHS: NA; Temperature: NA; Tolerance: NA; Voltage: NA; Wattage: NA; Weight: NA; Datasheet: NA
U4 = TCA9543APWR_TSSOP14: IC 2-CHANNEL I2C BUS SWITCH WITH INTERRUPT LOGIC AND RESET TSSOP14; Chkd/date: VASANTHA/060516; Crtd /date: VASANTHA/070316; Custom_Duty: 15%; Customs_HS_Code: 85423100; Distributor_name: DIGIKEY; Distributor_part_number: 296-42157-1-ND; Footprint Path: Y:\MIS_DATABASE\Library\ALTIUM_TOOL\PCB_FOOTPRINTS\Altium_Footprint_Lib.PcbLib; Height: 1.20MM; Library Path: Y:\MIS_DATABASE\Library\ALTIUM_TOOL\SCHEMATICS_PARTS\MS_BUSDRIVERTRANSCEIVER_Library.schlib; Manufacturer: TEXAS INSTRUMENTS; Mfr_name: TEXAS INSTRUMENTS; Mistral Part No: 141016030006-R; Package: TSSOP14; Part_type: ICS\DIGITAL\BUSTRANSCEIVER; Project: OCTASIC_3600; RoHS: RoHS; Temperature: -40°C+85°C; Tolerance: NA; Voltage: NA; Wattage: NA; Weight: NA; Datasheet: Y:\MIS_DATABASE\DATASHEETS\ICS\DIGITAL\BUSTRANSCEIVER\TCA9543A.PDF
U7 = TLV7103318D_WSON6: IC REGULATOR LDO LINEAR 200mA WSON6; Chkd/date: NAVEED/080415; Crtd /date: JEBRAN/300315; Custom_Duty: 15%; Customs_HS_Code: 85423100; Distributor_name: DIGIKEY; Distributor_part_number: 296-29058-1-ND; Height: 0.80MM; Manufacturer: TEXAS INSTRUMENTS; Mfr_name: TEXAS INSTRUMENTS; Mistral Part No: 142015030017-R; Package: WSON6; Part_type: ICS\POWER\VOLTAGE REGULATOR; Project: DUET BOARDS; RoHS: RoHS; Temperature: -40°C+125°C; Tolerance: NA; Voltage: NA; Wattage: NA; Weight: NA; Datasheet: Y:\MIS_DATABASE\DATASHEETS\MISC\REGULATORS\TLV71-SER.PDF
U97 = TCA9406DCUR_VSSOP8: IC VOLTAGE-LEVEL TRANSLATOR 2BIT BIDIRECTIONAL VSSOP8; Chkd/date: USMAN/190612; Crtd /date: BAVISH/210611; Custom_Duty: 15%; Customs_HS_Code: 85423100; Distributor_name: DIGIKEY; Distributor_part_number: 296-28109-1-ND; Footprint Path: Y:\MIS_DATABASE\Library\ALTIUM_TOOL\PCB_FOOTPRINTS\Altium_Footprint_Lib.PcbLib; Height: 0.90MM; Library Path: Y:\MIS_DATABASE\Library\ALTIUM_TOOL\SCHEMATICS_PARTS\MS_MISCINTERFACE_Library.schlib; Mfr_name: TEXAS INSTRUMENTS; Mistral Part No: 141011060026-R; Package: VSSOP8; Part_type: ICS\INTERFACE; Project: SVDU; RoHS: RoHS; Temperature: -40°C+85°C; Tolerance: NA; Voltage: NA; Wattage: NA; Weight: NA; Datasheet: Y:\MIS_DATABASE\DATASHEETS\ICS\INTERFACE\TCA9406.PDF
U98 = TXB0108RGYR_VQFN20: IC 8-BIT TRANSLATOR 15KV ESD VQFN20; Chkd/date: VASANTHA/221216; Crtd /date: MUDDU/190510; Custom_Duty: 15%; Customs_HS_Code: 85423100; Distributor_name: DIGIKEY; Distributor_part_number: 296-21528-1-ND; Height: 1.00MM; Mfr_name: TEXAS INSTRUMENTS; Mistral Part No: 141010050005-R; Package: VQFN20; Part_type: ICS\INTERFACE; Project: SHIVA; RoHS: Sb/ Br FREE; Temperature: -40°C+85°C; Tolerance: NA; Voltage: NA; Wattage: NA; Weight: 43mg; Datasheet: Y:\MIS_DATABASE\DATASHEETS\ICS\INTERFACE\TXB0108RGYR.PDF
C6 C413 = CAP: CAP CERAMIC 0.01uF 25V 10% X5R 0201; Chkd/date: MANIRAJA/230118; Crtd /date: MANIRAJA/230118; Custom_Duty: 15%; Customs_HS_Code: 85322990; Distributor_name: DIGIKEY; Distributor_part_number: GRM033R61E103KA12J-ND; Footprint Path: Y:\MIS_DATABASE\Library\ALTIUM_TOOL\PCB_FOOTPRINTS\Altium_Footprint_Lib.PcbLib; Height: 0.33MM; Library Path: Y:\MIS_DATABASE\Library\ALTIUM_TOOL\SCHEMATICS_PARTS\MS_DISCRETE_Library.schlib; Mfr_name: MURATA; Mfr_part_number: GRM033R61E103KA12J; Mistral Part No: 120018010007-R; Package: 0201; Part_type: CAPACITORS\CERAMIC; Project: TI_MAXIE_CPB; RoHS: RoHS; Temperature: -55°C+85°C; Tolerance: 10%; Voltage: 25V; Wattage: NA; Weight: 0.33mg; Datasheet: Y:\MIS_DATABASE\DATASHEETS\CAPACITORS\GRM033R61E103KA12.PDF
J12 = HEADER_2X1: CON HDR 1X2 2.54MM PITCH ST TH; Chkd/date: NAVEED/210714; Crtd /date: USMAN/031012; Custom_Duty: 24%; Customs_HS_Code: 85369090; Distributor_name: DIGIKEY; Distributor_part_number: WM8072-ND; Footprint Path: Y:\MIS_DATABASE\Library\ALTIUM_TOOL\PCB_FOOTPRINTS\Altium_Footprint_Lib.PcbLib; Height: 5.60MM; Library Path: Y:\MIS_DATABASE\Library\ALTIUM_TOOL\SCHEMATICS_PARTS\MS_CONNECTOR_Library.schlib; Mfr_name: MOLEX; Mfr_part_number: 90120-0122; Mistral Part No: 150012100005-R; Package: THRU-HOLE; Part_type: CONNECTOR\HEADERS; Project: NPOL_FEP; RoHS: RoHS; Temperature: -55°C+125°C; Tolerance: NA; Voltage: NA; Wattage: NA; Weight: 122mg; Datasheet: Y:\MIS_DATABASE\DATASHEETS\CONNECTORS\90120-XX.PDF
R10 = RESISTOR: RES 8.2K 1/20W 1% 0201; Chkd/date: SUHAS/230910; Crtd /date: MUDDU/060710; Custom_Duty: 15%; Customs_HS_Code: 85332119; Distributor_name: DIGIKEY; Distributor_part_number: 541-8.20KAABCT-ND; Footprint Path: Y:\MIS_DATABASE\Library\ALTIUM_TOOL\PCB_FOOTPRINTS\Altium_Footprint_Lib.PcbLib; Height: 0.28MM; Library Path: Y:\MIS_DATABASE\Library\ALTIUM_TOOL\SCHEMATICS_PARTS\MS_DISCRETE_Library.schlib; Mfr_name: VISHAY; Mfr_part_number: CRCW02018K20FKED; Mistral Part No: 110010070001-R; Package: 0201; Part_type: RESISTORS\FIXED; Project: PB_BUGBASE; RoHS: RoHS; Temperature: -55°C+155°C; Tolerance: 1%; Voltage: NA; Wattage: 1/20W; Weight: 0.17mg; Datasheet: Y:\MIS_DATABASE\DATASHEETS\RESISTORS\CRCW0201.PDF
R467 = RESISTOR: RES 0E 1/20W 5% 0201; Chkd/date: NAVEED/301214; Crtd /date: MUDDU/120710; Custom_Duty: 15%; Customs_HS_Code: 85332119; Distributor_name: DIGIKEY; Distributor_part_number: 311-0.0NCT-ND; Footprint Path: Y:\MIS_DATABASE\Library\ALTIUM_TOOL\PCB_FOOTPRINTS\Altium_Footprint_Lib.PcbLib; Height: 0.26MM; Library Path: Y:\MIS_DATABASE\Library\ALTIUM_TOOL\SCHEMATICS_PARTS\MS_DISCRETE_Library.schlib; Mfr_name: YAGEO AMERICA; Mfr_part_number: RC0201JR-070RL; Mistral Part No: 110010070067-R; Package: 0201; Part_type: RESISTORS\FIXED; Project: PB_BUGBASE; RoHS: RoHS; Temperature: -55°C+125°C; Tolerance: 5%; Voltage: NA; Wattage: 1/20W; Weight: 0.17mg; Datasheet: Y:\MIS_DATABASE\DATASHEETS\RESISTORS\RCXXXXL-SER_MAR18.PDF
TP3-TP8 = TESTPOINT: TESTPOINT CIR 20 SMD; Chkd/date: SHREESHAIL/171006; Crtd /date: MAZHAR/171006; Custom_Duty: NA; Customs_HS_Code: NA; Distributor_name: NA; Distributor_part_number: NA; Footprint Path: Y:\MIS_DATABASE\Library\ALTIUM_TOOL\PCB_FOOTPRINTS\Altium_Footprint_Lib.PcbLib; Height: NA; Library Path: Y:\MIS_DATABASE\Library\ALTIUM_TOOL\SCHEMATICS_PARTS\MS_DISCRETE_Library.schlib; MECHANICAL 3D STEP FILE: NA; Manufacturer: LOCAL; Mfr_name: LOCAL; Mistral Part No: NA; Package: SMD; Project: BT MODULE_CSRBC04; RoHS: NA; Temperature: NA; Tolerance: NA; Voltage: NA; Wattage: NA; Weight: NA; Datasheet: NA
U3 U70 = TCA6424ARGJR_QFN32: IC I2C I/O EXPANDER 24B UQFN32; Chkd/date: NAVEED/100715; Crtd /date: NAVEED/100914; Custom_Duty: 15%; Customs_HS_Code: 85423100; Distributor_name: DIGIKEY; Distributor_part_number: 296-27844-1-ND; Height: 0.60MM; Mfr_name: TEXAS INSTRUMENTS; Mistral Part No: 141014090009-R; Package: UQFN32; Part_type: ICS\DIGITAL\BUSTRANSCEIVER; Project: ZK_BIOMETRIC; RoHS: RoHS; Temperature: -40°C+85°C; Weight: NA; Datasheet: Y:\MIS_DATABASE\DATASHEETS\ICS\DIGITAL\BUSTRANSCEIVER\TCA6424AR.PDF
U39 = SN74CB3Q3257PWR_TSSOP16: IC 4BIT 1-OF-2 FET MULTIPLEXER/DEMULTIPLEXER TSSOP16; Chkd/date: SUHAS/251010; Crtd /date: USMAN/060109; Custom_Duty: 15%; Customs_HS_Code: 85423100; Distributor_name: DIGIKEY; Distributor_part_number: 296-19138-1-ND; Footprint Path: Y:\MIS_DATABASE\Library\ALTIUM_TOOL\PCB_FOOTPRINTS\Altium_Footprint_Lib.PcbLib; Footprint Ref: TSSOP16_25-59_205X180_1-2; Height: 1.20MM; Library Path: Y:\MIS_DATABASE\Library\ALTIUM_TOOL\SCHEMATICS_PARTS\MS_COMBINATIONAL_Library.schlib; MECHANICAL 3D STEP FILE: TSSOP16_25-59_205X180_1-2; Manufacturer: TEXAS INSTRUMENTS; Mfr_name: TEXAS INSTRUMENTS; Mistral Part No: 141009030117-R; Package: TSSOP16; Part_type: ICS\DIGITAL\COMBINATIONAL; Project: OMAP_EVM; RoHS: Sb/ Br FREE; Temperature: -40°C+85°C; Datasheet: Y:\MIS_DATABASE\DATASHEETS\ICS\DIGITAL\COMBINATIONAL\SN74CB3Q3257.PDF
U40 = TXB0104RUTR_UQFN12: IC 4-BIT BIDIRECTIONAL VOLTAGE-LEVEL TRANSLATOR UQFN12; Chkd/date: MANIRAJA/281117; Crtd /date: ALVY/271117; Custom_Duty: 15%; Customs_HS_Code: 85423100; Distributor_name: DIGIKEY; Distributor_part_number: 296-25888-1-ND; Height: 0.55MM; Manufacturer: TEXAS INSTRUMENTS; Mfr_name: TEXAS INSTRUMENTS; Mistral Part No: 141017110007-R; Package: UQFN12; Part_type: ICS\INTERFACE\LEVEL TRANSLATOR; Project: RSAPR_TYPE-II_3U-SBC; RoHS: RoHS; Temperature: -40°C+85°C; Tolerance: NA; Voltage: NA; Wattage: NA; Weight: 4.70mg; Datasheet: Y:\MIS_DATABASE\DATASHEETS\ICS\INTERFACE\TXB0104.PDF

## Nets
DGND: C1.2 C2.2 C4.2 C6.1 C12.2 C13.2 C14.2 C15.1 C178.1 C179.1 C180.1 C182.1 C183.1 C184.1 C193.1 C370.2 C379.1 C413.1 C477.1 C478.1 C479.1 C480.1 FL17.2 J1.12 J1.16 J1.24 J1.SH1 J1.SH2 J1.SH3 J1.SH4 J22.6 J22.7 J22.10 J22.13 J22.16 J22.19 J22.22 J22.25 J22.28 J22.31 J22.34 J22.37 J22.40 Q1.4(S1) Q1.7(S2) Q3.4(S1) Q3.7(S2) R4.2 R7.2 R11.1 R13.2 R20.2 R59.1 R162.1 R170.1 R180.1 R260.1 R280.1 R356.1 R470.1 R569.1 R570.1 R571.1 R572.1 R574.1 R576.1 U3.25(GND) U3.33(EP) U4.7(GND) U7.4(GND) U39.8(GND) U40.6(GND) U41.3(GND) U42.8(GND) U44.10(GND1) U44.11(GND2) U62.3(GND) U70.25(GND) U70.33(EP) U97.2(GND) U98.11(GND) U98.21(PAD) ; also on sheet 1 2 3 4 13 14 15 16 17 18 19 20 21 22 23 24 25 26 27 28 29 30 31 32 33 34 35 36 40 41 42 43
VCC1V8_SYS: C179.2 C184.2 U40.1(VCCA) U44.2(VCCB) ; also on sheet 4 16 19 20 22 25 34 40 42
VCC_3V3_SYS: C1.1 C2.1 C6.2 C15.2 C178.2 C180.2 C182.2 C183.2 C193.2 C370.1 C379.2 C413.2 C477.2 C479.2 FL18.2 J1.30 J1.32 J1.34 J1.36 R3.2 R6.1 R8.1 R9.2 R22.1 R23.1 R24.1 R25.1 R29.1 R30.1 R31.1 R33.1 R56.2 R151.1 R167.2 R172.2 R173.2 R179.2 R259.2 R278.2 R289.2 R407.2 R412.1 R463.2 R468.2 U3.27(VCCP) U3.31(VCC) U4.14(VCC) U39.16(VCC) U40.11(VCCB) U41.5(VCC) U42.16(VCC) U44.3(VCCA) U62.5(VCC) U70.27(VCCP) U70.31(VCC) U97.7(VCCB) U98.19(VCCB) ; also on sheet 1 4 15 16 19 20 21 23 24 26 27 29 30 31 32 33 34 36 40 41 42 43
VCC_5V0: C13.1 C14.1 U7.2(IN) U7.3(EN2) ; also on sheet 13 14 33 35 41
VCC_CSI_IO: C4.1 C12.1 C478.2 C480.2 J1.38 J1.40 R16.2 R19.2 R20.1 R567.1 R568.1 R573.2 R575.2 U97.3(VCCA) U98.2(VCCA)
ADDR_IO_EXP: R470.2 U70.26(ADDR)
ADDR_IO_EXP1: R9.1 U3.26(ADDR)
BT_UART_WAKE_SOC: U70.12(P13) ; also on sheet 19
CH1_LVDS_A0N: J22.11 U12.AA2(OLDI0_A0N)
CH1_LVDS_A0P: J22.12 U12.AA3(OLDI0_A0P)
CH1_LVDS_A1N: J22.14 U12.V5(OLDI0_A1N)
CH1_LVDS_A1P: J22.15 U12.V6(OLDI0_A1P)
CH1_LVDS_A2N: J22.20 U12.U7(OLDI0_A2N)
CH1_LVDS_A2P: J22.21 U12.U6(OLDI0_A2P)
CH1_LVDS_A3N: J22.23 U12.W6(OLDI0_A3N)
CH1_LVDS_A3P: J22.24 U12.W5(OLDI0_A3P)
CH1_LVDS_CLKN: J22.17 U12.V7(OLDI0_CLK0N)
CH1_LVDS_CLKP: J22.18 U12.V8(OLDI0_CLK0P)
CH2_LVDS_A0N: J22.26 U12.AA4(OLDI0_A4N)
CH2_LVDS_A0P: J22.27 U12.Y5(OLDI0_A4P)
CH2_LVDS_A1N: J22.29 U12.AA6(OLDI0_A5N)
CH2_LVDS_A1P: J22.30 U12.AA5(OLDI0_A5P)
CH2_LVDS_A2N: J22.35 U12.AA10(OLDI0_A6N)
CH2_LVDS_A2P: J22.36 U12.Y9(OLDI0_A6P)
CH2_LVDS_A3N: J22.38 U12.AA8(OLDI0_A7N)
CH2_LVDS_A3P: J22.39 U12.Y8(OLDI0_A7P)
CH2_LVDS_CLKN: J22.32 U12.Y7(OLDI0_CLK1N)
CH2_LVDS_CLKP: J22.33 U12.AA7(OLDI0_CLK1P)
CSI0_RXCLKN: J1.7 U12.AA14(CSI0_RXCLKN)
CSI0_RXCLKP: J1.5 U12.AA13(CSI0_RXCLKP)
CSI0_RXN0: J1.11 U12.Y13(CSI0_RXN0)
CSI0_RXN1: J1.15 U12.V13(CSI0_RXN1)
CSI0_RXN2: J1.19 U12.U12(CSI0_RXN2)
CSI0_RXN3: J1.23 U12.W12(CSI0_RXN3)
CSI0_RXP0: J1.9 U12.Y12(CSI0_RXP0)
CSI0_RXP1: J1.13 U12.V12(CSI0_RXP1)
CSI0_RXP2: J1.17 U12.U11(CSI0_RXP2)
CSI0_RXP3: J1.21 U12.W11(CSI0_RXP3)
CSI0_RXRCALIB: R356.2 U12.T11(CSI0_RXRCALIB)
CSI_GPIO0: U70.14(P15) U98.20(B1)
CSI_GPIO0_buff: J1.6 U98.1(A1)
CSI_GPIO1: U70.15(P16) U98.18(B2)
CSI_GPIO1_buff: J1.8 U98.3(A2)
CSI_GPIO2: U98.17(B3) ; also on sheet 42
CSI_GPIO2_buff: J1.18 U98.4(A3)
CSI_GPIO3: U98.16(B4) ; also on sheet 42
CSI_GPIO3_buff: J1.20 U98.5(A4)
CSI_GPIO4: U98.15(B5) ; also on sheet 42
CSI_GPIO4_buff: J1.22 U98.6(A5)
CSI_I2C2_nINT1: R22.2 U4.8(~{INT1})
CSI_I2C2_SCL: R24.2 U4.10(SC1) U97.8(SCL_B)
CSI_I2C2_SCL_BUFF: J1.2 R567.2 U97.5(SCL_A)
CSI_I2C2_SDA: R23.2 U4.9(SD1) U97.1(SDA_B)
CSI_I2C2_SDA_BUFF: J1.4 R568.2 U97.4(SDA_A)
CSI_I2C_LT_EN: R575.1 R576.2 U97.6(OE)
CSI_LT_EN: R573.1 R574.2 U98.10(OE)
CSI_REFCLK: J1.10 TP2.1(TP) ; also on sheet 25
CSI_RSTz: R4.1 U3.10(P11) U98.14(B6)
CSI_RSTz_buff: J1.14 U98.7(A6)
CSI_VLDO_SEL: R13.1 U3.23(P26) U7.1(EN1)
EEPROM_VDD: FL18.1 J22.1
EXP_HAT_DETECT: R173.1 U70.8(P07) ; also on sheet 33
EXP_I2C2_nINT0: R6.2 U4.4(~{INT0})
EXP_I2C2_SCL: R33.2 U4.6(SC0) ; also on sheet 33
EXP_I2C2_SDA: R31.2 U4.5(SD0) ; also on sheet 33
EXP_PS_3V3_EN: U70.6(P05) ; also on sheet 33
EXP_PS_5V0_EN: U70.7(P06) ; also on sheet 33
EXP_SPI2_CLK: U42.5(2B1) ; also on sheet 33
EXP_SPI2_CS0/EHRPWM0_A: U42.2(1B1) ; also on sheet 33
EXP_SPI2_D0: U42.11(3B1) ; also on sheet 33
EXP_SPI2_D1/ECAP2_IN_APWM_OUT: U42.14(4B1) ; also on sheet 33
GPIO1_23_INTn: R467.1 ; also on sheet 42 43
GPIO_AUD_RSTn: U70.9(P10) ; also on sheet 40
GPIO_CPSW1_RST: U70.2(P01) ; also on sheet 24
GPIO_CPSW2_RST: U70.1(P00) ; also on sheet 1
GPIO_eMMC_RSTn: U70.10(P11) ; also on sheet 20
GPIO_HDMI_RSTn: U70.13(P14) ; also on sheet 41
GPIO_OLDI_RSTn: R407.1 U3.19(P22) U62.1(A)
HDMI_INTn: U70.17(P20) ; also on sheet 41
IO_EXP1_INTn: R3.1 U3.32(~{INT})
IO_EXP_INTn: R467.2 R468.1 U70.32(~{INT})
IO_EXP_TEST_LED: R168.1 R170.2 U70.24(P27)
LVDS_SHIELD: FL17.1 J22.SH1 J22.SH2 J22.SH3 J22.SH4
MCASP1_ACLKX_AUD: U39.3(1B2) ; also on sheet 40
MCASP1_ACLKX_BT: U40.5(A4) ; also on sheet 19
MCASP1_ACLKX_BUF: U39.4(1A) U40.7(B4) ; also on sheet 32
MCASP1_ACLKX_HDMI: U39.2(1B1) ; also on sheet 41
MCASP1_AFSX_AUD: U39.6(2B2) ; also on sheet 40
MCASP1_AFSX_BT: U40.4(A3) ; also on sheet 19
MCASP1_AFSX_BUF: U39.7(2A) U40.8(B3) ; also on sheet 32
MCASP1_AFSX_HDMI: U39.5(2B1) ; also on sheet 41
MCASP1_AXR0_AUD: U39.10(3B2) ; also on sheet 40
MCASP1_AXR0_BT: U40.3(A2) ; also on sheet 19
MCASP1_AXR0_BUF: U39.9(3A) U40.9(B2) ; also on sheet 32
MCASP1_AXR0_HDMI: U39.11(3B1) ; also on sheet 41
MCASP1_AXR2_AUD: U39.13(4B2) ; also on sheet 40
MCASP1_AXR2_BT: U40.2(A1) ; also on sheet 19
MCASP1_AXR2_BUF: U39.12(4A) U40.10(B1) ; also on sheet 32
MCASP1_BUF_BT_EN: R10.2 U70.20(P23)
MCASP1_BUF_BT_EN_1V8: R10.1 R11.2 U40.12(OE)
MCASP1_FET_EN: R259.1 R260.2 U39.15(~{OE}) U70.19(P22)
MCASP1_FET_SEL: J12.1 R172.1 U39.1(S) U70.21(P24)
MMC1_SD_EN: U70.4(P03) ; also on sheet 21
OLDI_RESETn: J22.8 R412.2 U62.4(Y)
PRU_3V3_EN: U3.20(P23) ; also on sheet 32
PRU_DETECT: R463.1 U70.3(P02) ; also on sheet 32
RESETSTATz: U3.28(~{RESET}) U4.3(~{RESET}) U62.2(B) U70.28(~{RESET}) ; also on sheet 1 4 20 21 22 24 27 32 40 41 42
SOC_GPIO1_49: R59.2 R60.1 ; also on sheet 20
SoC_I2C0_SCL: J22.2 ; also on sheet 4 13 23 32 33 42
SoC_I2C0_SDA: J22.3 ; also on sheet 4 13 23 32 33 42
SOC_I2C1_SCL: U3.29(SCL) U70.29(SCL) ; also on sheet 16 23 26 40 41 42
SOC_I2C1_SDA: U3.30(SDA) U70.30(SDA) ; also on sheet 16 23 26 40 41 42
SoC_I2C2_SCL: R30.2 U4.12(SCL) ; also on sheet 32
SoC_I2C2_SDA: R29.2 U4.13(SDA) ; also on sheet 32
SOC_SPI2_CLK: U42.7(2A) U44.8(2A1) ; also on sheet 33
SOC_SPI2_CS0: U42.4(1A) U44.6(1A1) ; also on sheet 33
SOC_SPI2_D0: U42.9(3A) U44.7(1A2) ; also on sheet 33
SOC_SPI2_D1: U42.12(4A) U44.9(2A2) ; also on sheet 33
SOC_UART1_CTS: U42.10(3B2) ; also on sheet 31
SOC_UART1_CTS_BT: U44.14(1B2) ; also on sheet 19
SOC_UART1_RTS: U42.13(4B2) ; also on sheet 31
SOC_UART1_RTS_BT: U44.12(2B2) ; also on sheet 19
SOC_UART1_RX_BT: U44.15(1B1) ; also on sheet 19
SOC_UART1_RXD: U42.3(1B2) ; also on sheet 31
SOC_UART1_TX_BT: U44.13(2B1) ; also on sheet 19
SOC_UART1_TXD: U42.6(2B2) ; also on sheet 31
SoC_WLAN_SDIO_RST: U3.24(P27) ; also on sheet 19
SPI0_FET_OE: U3.18(P21) ; also on sheet 42
SPI0_FET_SEL: U3.17(P20) ; also on sheet 42
TEST_GPIO2: U70.18(P21) ; also on sheet 26 28
TS_INT#: J22.9 R151.2 U70.16(P17)
UART1_FET_BUF_EN: R289.1 U41.2(A) U44.1(~{1OE}) U44.16(~{2OE}) U70.11(P12)
UART1_FET_BUF_EN_INV: U41.4(Y) U42.15(~{OE})
UART1_FET_SEL: R179.1 R180.2 U42.1(S) U70.22(P25)
VLDO_CSI_1V8: R19.1 U7.5(OUT2)
VLDO_CSI_3V3: R16.1 U7.6(OUT1)
VPP_LDO_EN: U70.5(P04) ; also on sheet 15
WL_LT_EN: U3.9(P10) ; also on sheet 19
N18904630: LD3.1(CATHODE) Q1.1(D1) Q1.2(D2) Q1.5(D3) Q1.6(D4) Q1.8(D5)
N18904632: Q1.3(G) R60.2
N18904656: LD3.2(ANODE) R56.1
N18904815: LD7.1(CATHODE) Q3.1(D1) Q3.2(D2) Q3.5(D3) Q3.6(D4) Q3.8(D5)
N18904817: Q3.3(G) R168.2
N18904841: LD7.2(ANODE) R167.1
N20878915: R8.2 U4.1(A0)
N20878927: R7.1 U4.2(A1)
N20878931: R25.2 U4.11(~{INT})
N20933818: R280.2 U44.4(1DIR)
N20933822: R278.1 U44.5(2DIR)
N20936712: J12.2 R162.2
N21197992: TP8.1(TP) U3.16(P17)
N21197993: TP7.1(TP) U3.15(P16)
N21197994: TP5.1(TP) U3.13(P14)
N21197995: TP6.1(TP) U3.14(P15)
N21197996: TP4.1(TP) U3.12(P13)
N21198784: TP3.1(TP) U3.11(P12)
N21763900: R570.2 U98.13(B7)
N21763905: R569.2 U98.12(B8)
N21763910: R572.2 U98.9(A8)
N21763915: R571.2 U98.8(A7)

Not connected (* = marked no-connect by the designer): J1 1* 3* 25* 26* 27* 28* 29* 31* 33* 35* 37* 39*; J22 4* 5*; U3 1(P00)* 2(P01)* 3(P02)* 4(P03)* 5(P04)* 6(P05)* 7(P06)* 8(P07)* 21(P24)* 22(P25)*; U12 T13(RSVD5) T14(RSVD6); U39 14(4B1)*; U41 1(NC)*; U70 23(P26)*

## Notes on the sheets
sheet 37
- OLDI DISPLAY INTERFACE
- D-Note:-
  Add a series resistor to the GPIO
  input for isolation or testing
  Refer SK-AM62P-LP schematics
- 100E
- 100E
- 100E
- 100E
- D-Note:-
  Add a cap after the ferrite
  to minimize resonance
- 100E
- 100E
- 100E
- 100E
- 100E
- 100E
- D-Note :-
  Refer Device Comparison for information on the
  AMC package device that supports OLDI interface
- SoC UART1 FET SWITCH & BUFFER
- INPUT/OUTPUT
- OEn
- SEL
- An
- L
- L
- An=nB1
- USER EXPANSION CONNECTOR
- L
- H(DEFAULT)
- An=nB2
- SOC - FT4232
- SoC_MAIN_UART1_RXD
- SoC_MAIN_UART1_RXD
- SoC_MAIN_UART1_CTS
- SoC_MAIN_UART1_CTS
- SoC_MAIN_UART1_TXD
- SoC_MAIN_UART1_TXD
- SoC_MAIN_UART1_RTS
- SoC_MAIN_UART1_RTS
- 2DIR=H : 2A ->2B
  1DIR=L : 1B ->1A
sheet 38
- CSI INTERFACE
- R-Note :-
  Based on End product requirement, interface
  the CSI signals to respective attach devices
- MIPI Connector
- 100E
- Silk: CSI0 EXP
- 100E
- 100E
- [SCL]
- [SDA]
- 100E
- [GPIO/PWM_A]
- 3.3V
- [GPIO/PWM_B]
- 100E
- [25MHz_REFCLK]
- [RESETz]
- [MOSI/GPIO]
- Reserved Pins
- [SCLK/GPO]
- [CS/GPIO]
- [3V3]
- [VIO]
- MIPI SIDE
- SOC SIDE
- (VCCA < OR = VCCB)
- (VCCA < or = VCCB)
- CSI_VLDO_SEL
- LDO VTG
- I2C SWITCH FOR SoC_I2C2
- LOW
- 1.8V (Default)
- Note: 1K res is to bleed off the voltage.
- High
- 3.3V
- Enabled through IO Expander.
- USER TEST LEDS
- I2C ADDRESS: 0x71
- SoC GPIO
- IO EXP GPIO
- R-Note :-
  All the I2C outputs are disabled by default
sheet 39
- IO EXPANDER
- D-Note :-
  Add additional decap
  Verify and terminate unused IOs
- [GPIO/PWM_A]
- [GPIO/PWM_B]
- I2C ADDRESS: 0x22
- I2C ADDRESS: 0x23
- McASP1 FET SWITCH & BUFFER
- INPUT/OUTPUT
- OEn
- SEL
- An
- L
- H(DEFAULT)
- An=nB2
- MCASP1 - CODEC
- L
- L
- An=nB1
- MCASP1 - HDMI
- DIR=H : A ->B
  DIR=L : B ->A
- (VCCA < or = VCCB)
